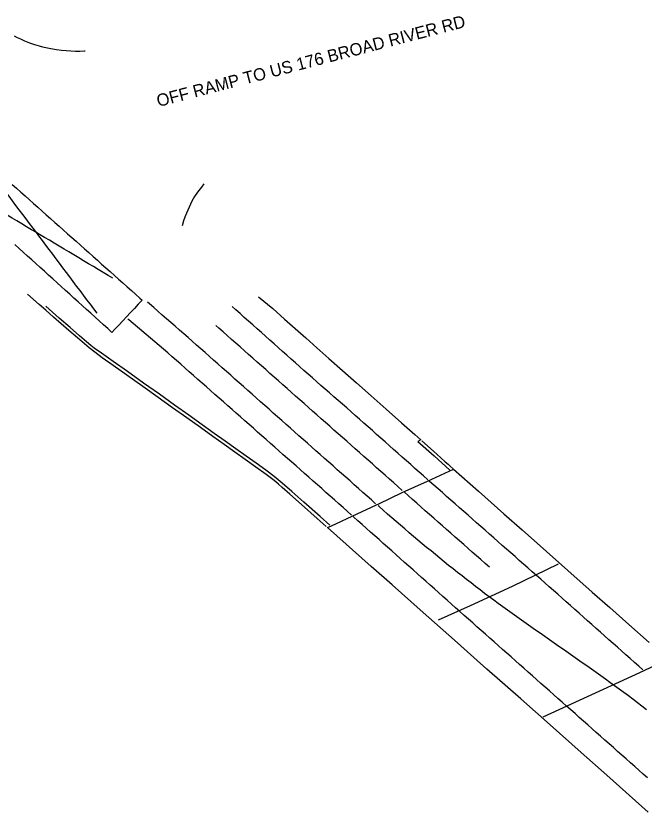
# Model space of a CAD drawing. Extents: x 1970211 to 1973046, y 801032 to 804001.
# Drawn here: x 1971353.3 to 1971628.9, y 802598.6 to 802947.9 of the extents above; entities that cross this region are included whole.
import ezdxf

# ---------------------------------------------------------------- set-up
doc = ezdxf.new("R2010")
doc.units = 0
for name, color, linetype in [('RD_EX_Bridge', 7, 'Continuous'), ('RD_EX_Bridge_Seam', 7, 'Continuous'), ('RD_EX_Conc', 7, 'Continuous'), ('RD_EX_Road', 7, 'Continuous'), ('RD_EX_Road_Paint', 7, 'Continuous'), ('RD_TX_RoadID', 7, 'Continuous')]:
    doc.layers.add(name, color=color, linetype=linetype)

msp = doc.modelspace()

# ---------------------------------------------------------------- linework, layer by layer
at = {"layer": 'RD_EX_Bridge'}
msp.add_lwpolyline([(1971630.72, 802598.58), (1971612.51, 802614.79), (1971601.37, 802624.67), (1971587.66, 802636.8), (1971574.86, 802648.23), (1971559.98, 802661.35), (1971547.12, 802672.78), (1971530.66, 802687.37), (1971518.33, 802698.31), (1971509.24, 802706.38), (1971490.01, 802723.38), (1971491.81, 802724.23), (1971503.02, 802729.5), (1971511.49, 802733.4), (1971512.58, 802733.88), (1971522.85, 802738.84), (1971533.82, 802743.75), (1971543.35, 802748.09), (1971545.36, 802749), (1971556.21, 802739.43), (1971567.44, 802729.46), (1971575.43, 802722.36), (1971586.15, 802712.88), (1971595.51, 802704.6), (1971606.18, 802695.11), (1971613.91, 802688.28), (1971622.19, 802680.91), (1971631.17, 802672.94)], dxfattribs=at)
at = {"layer": 'RD_EX_Bridge_Seam'}
for points in [[(1971538.66, 802682.92), (1971552.7, 802689.2), (1971571.13, 802697.75), (1971591.33, 802707.51)], [(1971584.66, 802640.4), (1971611.14, 802652.5), (1971618.12, 802655.75), (1971629.02, 802660.65), (1971639.02, 802665.54)]]:
    msp.add_lwpolyline(points, dxfattribs=at)
at = {"layer": 'RD_EX_Conc'}
for points in [[(1971352.57, 802939.14), (1971353.88, 802938.45), (1971355.31, 802937.78), (1971357.15, 802936.96), (1971359.26, 802936.12), (1971361.52, 802935.36), (1971363.54, 802934.75), (1971364.95, 802934.34), (1971366.42, 802933.99), (1971368.64, 802933.56), (1971371.11, 802933.16), (1971373.35, 802932.9), (1971375.43, 802932.72), (1971377.44, 802932.56), (1971379.41, 802932.46), (1971381.41, 802932.49), (1971383.44, 802932.54), (1971383.74, 802932.55)], [(1971435.83, 802874.15), (1971434.67, 802872.77), (1971432.96, 802870.54), (1971431.68, 802868.6), (1971430.54, 802866.54), (1971429.28, 802863.92), (1971428.15, 802861.39), (1971427.41, 802859.57), (1971426.84, 802857.91), (1971426.23, 802855.85)], [(1971489.45, 802723.91), (1971485.48, 802727.4), (1971478.62, 802733.46), (1971473.43, 802738.05), (1971470.11, 802741.02), (1971468.47, 802742.5), (1971467.28, 802743.54), (1971466.06, 802744.51), (1971463.15, 802746.65), (1971458.57, 802749.97), (1971453.9, 802753.32), (1971449.36, 802756.55), (1971444.68, 802759.89), (1971439.75, 802763.41), (1971434.28, 802767.31), (1971428.26, 802771.57), (1971422.08, 802775.96), (1971415.75, 802780.46), (1971409.02, 802785.25), (1971402.05, 802790.21), (1971396.04, 802794.49), (1971391.23, 802797.93), (1971387.88, 802800.36), (1971385.45, 802802.24), (1971380.34, 802806.58), (1971376.56, 802809.85), (1971369.82, 802815.71), (1971366.37, 802818.72), (1971363.47, 802821.26), (1971358.41, 802825.74)], [(1971531.34, 802761.53), (1971536.5, 802756.91), (1971539.77, 802753.98), (1971541.71, 802752.24), (1971542.9, 802751.19), (1971543.89, 802750.31), (1971545.1, 802749.23)]]:
    msp.add_lwpolyline(points, dxfattribs=at)
at = {"layer": 'RD_EX_Road'}
for points in [[(1971459.76, 802824.6), (1971466.02, 802819.47), (1971471.17, 802814.9), (1971475.84, 802810.76), (1971480.5, 802806.61), (1971485.32, 802802.32), (1971490.65, 802797.56), (1971496.54, 802792.33), (1971502.73, 802786.85), (1971509.17, 802781.17), (1971515.78, 802775.31), (1971522.44, 802769.41), (1971528.35, 802764.17), (1971530.99, 802761.84), (1971529.62, 802761.12), (1971536.75, 802754.83), (1971543.73, 802748.66)], [(1971491.09, 802724.52), (1971486.83, 802728.25), (1971479.64, 802734.57), (1971474.3, 802739.28), (1971470.08, 802742.94), (1971466.67, 802745.75), (1971462.91, 802748.61), (1971458.67, 802751.65), (1971454.28, 802754.76), (1971449.79, 802757.95), (1971445.17, 802761.25), (1971440.35, 802764.7), (1971435.04, 802768.49), (1971429.2, 802772.65), (1971422.92, 802777.12), (1971416.24, 802781.88), (1971409.29, 802786.82), (1971402.24, 802791.82), (1971395.98, 802796.24), (1971390.8, 802799.88), (1971387.63, 802802.15), (1971386.23, 802803.24), (1971384.22, 802804.95), (1971381.2, 802807.58), (1971377.11, 802811.13), (1971372.24, 802815.34), (1971366.46, 802820.56)]]:
    msp.add_lwpolyline(points, dxfattribs=at)
at = {"layer": 'RD_EX_Road_Paint'}
for points in [[(1971362.33, 802852.81), (1971360.82, 802854.8), (1971359.32, 802856.8), (1971357.82, 802858.79), (1971356.31, 802860.79), (1971354.81, 802862.79), (1971353.31, 802864.78), (1971351.8, 802866.78), (1971350.3, 802868.78), (1971348.79, 802870.77), (1971347.29, 802872.77), (1971345.79, 802874.76), (1971344.28, 802876.76), (1971342.78, 802878.76), (1971341.28, 802880.75), (1971339.77, 802882.75), (1971338.27, 802884.75), (1971338.19, 802884.85)], [(1971362.33, 802852.81), (1971360.18, 802854.09), (1971358.03, 802855.37), (1971355.89, 802856.65), (1971353.74, 802857.93), (1971351.6, 802859.21), (1971349.45, 802860.49), (1971347.3, 802861.77), (1971345.16, 802863.05), (1971343.01, 802864.33), (1971340.87, 802865.61), (1971338.72, 802866.89), (1971336.58, 802868.17), (1971334.43, 802869.45), (1971332.28, 802870.73), (1971330.14, 802872.01), (1971327.99, 802873.29), (1971325.85, 802874.57), (1971323.7, 802875.85), (1971322.18, 802876.76)], [(1971351.72, 802873.92), (1971353.59, 802872.26), (1971355.45, 802870.6), (1971357.32, 802868.94), (1971359.19, 802867.28), (1971361.05, 802865.61), (1971362.92, 802863.95), (1971364.79, 802862.29), (1971366.65, 802860.63), (1971368.52, 802858.97), (1971370.39, 802857.31), (1971372.25, 802855.65), (1971374.12, 802853.99), (1971375.99, 802852.33), (1971377.85, 802850.66), (1971379.72, 802849), (1971381.59, 802847.34), (1971383.45, 802845.68), (1971385.32, 802844.02), (1971387.19, 802842.36), (1971389.05, 802840.7), (1971390.92, 802839.04), (1971392.79, 802837.38), (1971394.65, 802835.71), (1971396.52, 802834.05), (1971398.39, 802832.39), (1971400.25, 802830.73), (1971402.12, 802829.07), (1971403.99, 802827.41), (1971405.85, 802825.75), (1971407.72, 802824.09), (1971408.68, 802823.23), (1971406.98, 802821.4), (1971405.28, 802819.57), (1971403.57, 802817.74), (1971401.87, 802815.91), (1971400.17, 802814.08), (1971398.46, 802812.25), (1971396.76, 802810.42), (1971395.47, 802809.03)], [(1971388.99, 802817.4), (1971387.49, 802819.39), (1971385.99, 802821.39), (1971384.48, 802823.39), (1971382.98, 802825.38), (1971381.48, 802827.38), (1971379.97, 802829.38), (1971378.47, 802831.37), (1971376.97, 802833.37), (1971375.46, 802835.36), (1971373.96, 802837.36), (1971372.46, 802839.36), (1971370.95, 802841.35), (1971369.45, 802843.35), (1971367.94, 802845.35), (1971366.44, 802847.34), (1971364.94, 802849.34), (1971363.43, 802851.33), (1971362.33, 802852.81)], [(1971395.87, 802832.79), (1971393.73, 802834.07), (1971391.58, 802835.35), (1971389.44, 802836.63), (1971387.29, 802837.91), (1971385.14, 802839.19), (1971383, 802840.47), (1971380.85, 802841.75), (1971378.71, 802843.03), (1971376.56, 802844.31), (1971374.42, 802845.59), (1971372.27, 802846.87), (1971370.12, 802848.15), (1971367.98, 802849.43), (1971365.83, 802850.71), (1971363.69, 802851.99), (1971362.33, 802852.81)], [(1971395.47, 802809.03), (1971393.62, 802810.71), (1971391.76, 802812.38), (1971389.91, 802814.06), (1971388.05, 802815.74), (1971386.2, 802817.41), (1971384.35, 802819.09), (1971382.49, 802820.76), (1971380.64, 802822.44), (1971378.79, 802824.11), (1971376.93, 802825.79), (1971375.08, 802827.47), (1971373.23, 802829.14), (1971371.37, 802830.82), (1971369.52, 802832.49), (1971367.66, 802834.17), (1971365.81, 802835.85), (1971363.96, 802837.52), (1971362.1, 802839.2), (1971360.25, 802840.87), (1971358.4, 802842.55), (1971356.54, 802844.22), (1971354.69, 802845.9), (1971352.84, 802847.58)], [(1971511.13, 802733.87), (1971509.26, 802735.53), (1971507.39, 802737.2), (1971505.52, 802738.86), (1971503.66, 802740.52), (1971501.79, 802742.18), (1971499.92, 802743.84), (1971498.05, 802745.49), (1971496.18, 802747.15), (1971494.31, 802748.81), (1971492.44, 802750.47), (1971490.57, 802752.12), (1971488.69, 802753.78), (1971486.82, 802755.43), (1971484.95, 802757.09), (1971483.08, 802758.75), (1971481.21, 802760.4), (1971479.34, 802762.06), (1971477.47, 802763.72), (1971475.6, 802765.38), (1971473.73, 802767.03), (1971471.86, 802768.69), (1971469.99, 802770.35), (1971468.12, 802772.01), (1971466.25, 802773.66), (1971464.38, 802775.32), (1971462.51, 802776.98), (1971460.64, 802778.64), (1971458.77, 802780.29), (1971456.9, 802781.95), (1971455.03, 802783.61), (1971453.16, 802785.27), (1971451.29, 802786.92), (1971449.42, 802788.58), (1971447.55, 802790.24), (1971445.68, 802791.9), (1971443.81, 802793.55), (1971441.94, 802795.21), (1971440.07, 802796.87), (1971438.2, 802798.53), (1971436.33, 802800.18), (1971434.46, 802801.84), (1971432.59, 802803.49), (1971430.7, 802805.14), (1971428.82, 802806.78), (1971426.94, 802808.43), (1971425.06, 802810.07), (1971423.18, 802811.72), (1971421.3, 802813.36), (1971419.42, 802815.01), (1971417.54, 802816.65), (1971415.65, 802818.3), (1971413.77, 802819.94), (1971411.89, 802821.58), (1971411.04, 802822.33)], [(1971533.98, 802744.38), (1971532.11, 802746.04), (1971530.24, 802747.7), (1971528.38, 802749.36), (1971526.51, 802751.02), (1971524.64, 802752.68), (1971522.77, 802754.34), (1971520.9, 802756), (1971519.03, 802757.66), (1971517.16, 802759.32), (1971515.3, 802760.98), (1971513.43, 802762.64), (1971511.56, 802764.3), (1971509.69, 802765.96), (1971507.82, 802767.62), (1971505.95, 802769.28), (1971504.09, 802770.94), (1971502.22, 802772.59), (1971500.33, 802774.24), (1971498.45, 802775.88), (1971496.57, 802777.53), (1971494.69, 802779.17), (1971492.81, 802780.82), (1971490.93, 802782.46), (1971489.04, 802784.11), (1971487.16, 802785.75), (1971485.28, 802787.4), (1971483.4, 802789.04), (1971481.52, 802790.69), (1971479.66, 802792.35), (1971477.79, 802794.01), (1971475.93, 802795.68), (1971474.06, 802797.34), (1971472.19, 802799), (1971470.33, 802800.66), (1971468.46, 802802.32), (1971466.6, 802803.98), (1971464.73, 802805.65), (1971462.86, 802807.31), (1971461, 802808.97), (1971459.13, 802810.63), (1971457.26, 802812.29), (1971455.39, 802813.95), (1971453.53, 802815.61), (1971451.66, 802817.27), (1971449.79, 802818.93), (1971448.18, 802820.36)], [(1971500.56, 802728.89), (1971498.69, 802730.55), (1971496.82, 802732.21), (1971494.95, 802733.87), (1971493.08, 802735.52), (1971491.21, 802737.18), (1971489.34, 802738.84), (1971487.47, 802740.5), (1971485.6, 802742.16), (1971483.73, 802743.82), (1971481.87, 802745.48), (1971479.99, 802747.13), (1971478.12, 802748.78), (1971476.24, 802750.44), (1971474.37, 802752.09), (1971472.49, 802753.74), (1971470.62, 802755.39), (1971468.74, 802757.05), (1971466.87, 802758.7), (1971465, 802760.35), (1971463.12, 802762), (1971461.25, 802763.66), (1971459.37, 802765.31), (1971457.5, 802766.96), (1971455.62, 802768.61), (1971453.75, 802770.26), (1971451.87, 802771.92), (1971450, 802773.57), (1971448.13, 802775.22), (1971446.25, 802776.87), (1971444.38, 802778.53), (1971442.5, 802780.18), (1971440.63, 802781.83), (1971438.75, 802783.48), (1971436.88, 802785.14), (1971435, 802786.79), (1971433.13, 802788.44), (1971431.25, 802790.09), (1971429.38, 802791.74), (1971427.51, 802793.4), (1971425.63, 802795.05), (1971423.76, 802796.7), (1971421.88, 802798.35), (1971420.01, 802800.01), (1971418.11, 802801.63), (1971416.2, 802803.24), (1971414.29, 802804.86), (1971412.38, 802806.47), (1971410.48, 802808.08), (1971408.57, 802809.7), (1971406.66, 802811.31), (1971404.75, 802812.92), (1971402.84, 802814.54), (1971402.44, 802814.88)], [(1971522.81, 802739.72), (1971520.94, 802741.38), (1971519.07, 802743.03), (1971517.2, 802744.69), (1971515.32, 802746.34), (1971513.45, 802748), (1971511.58, 802749.66), (1971509.71, 802751.31), (1971507.84, 802752.97), (1971505.97, 802754.62), (1971504.09, 802756.28), (1971502.22, 802757.93), (1971500.35, 802759.59), (1971498.48, 802761.25), (1971496.61, 802762.9), (1971494.74, 802764.56), (1971492.86, 802766.21), (1971490.99, 802767.87), (1971489.12, 802769.52), (1971487.25, 802771.18), (1971485.38, 802772.84), (1971483.51, 802774.49), (1971481.63, 802776.15), (1971479.76, 802777.8), (1971477.89, 802779.46), (1971476.02, 802781.12), (1971474.15, 802782.77), (1971472.28, 802784.43), (1971470.4, 802786.08), (1971468.53, 802787.74), (1971466.66, 802789.39), (1971464.79, 802791.05), (1971462.92, 802792.71), (1971461.05, 802794.36), (1971459.17, 802796.02), (1971457.3, 802797.67), (1971455.43, 802799.33), (1971453.56, 802800.99), (1971451.69, 802802.64), (1971449.82, 802804.3), (1971447.94, 802805.95), (1971446.07, 802807.61), (1971444.2, 802809.26), (1971442.33, 802810.92), (1971441.06, 802812.04)], [(1971628.42, 802660.92), (1971626.55, 802662.58), (1971624.69, 802664.25), (1971622.82, 802665.91), (1971620.95, 802667.57), (1971619.08, 802669.23), (1971617.21, 802670.89), (1971615.34, 802672.55), (1971613.48, 802674.21), (1971611.61, 802675.87), (1971609.74, 802677.53), (1971607.87, 802679.19), (1971606, 802680.85), (1971604.13, 802682.51), (1971602.27, 802684.17), (1971600.4, 802685.83), (1971598.53, 802687.49), (1971596.66, 802689.15), (1971594.79, 802690.81), (1971592.92, 802692.47), (1971591.05, 802694.13), (1971589.19, 802695.79), (1971587.31, 802697.45), (1971585.44, 802699.1), (1971583.56, 802700.75), (1971581.69, 802702.4), (1971579.81, 802704.05), (1971577.94, 802705.7), (1971576.06, 802707.36), (1971574.18, 802709.01), (1971572.31, 802710.66), (1971570.43, 802712.31), (1971568.56, 802713.96), (1971566.68, 802715.61), (1971564.8, 802717.26), (1971562.93, 802718.92), (1971561.05, 802720.57), (1971559.18, 802722.22), (1971557.3, 802723.87), (1971555.43, 802725.52), (1971553.55, 802727.17), (1971551.67, 802728.83), (1971549.8, 802730.48), (1971547.92, 802732.13), (1971546.05, 802733.78), (1971544.17, 802735.43), (1971542.29, 802737.08), (1971540.42, 802738.74), (1971538.54, 802740.39), (1971536.67, 802742.04), (1971534.79, 802743.69), (1971534.67, 802743.8)], [(1971561.06, 802706.03), (1971559.18, 802707.69), (1971557.3, 802709.34), (1971555.43, 802710.99), (1971553.55, 802712.64), (1971551.67, 802714.29), (1971549.8, 802715.94), (1971547.92, 802717.59), (1971546.05, 802719.24), (1971544.17, 802720.89), (1971542.29, 802722.55), (1971540.42, 802724.2), (1971538.54, 802725.85), (1971536.67, 802727.5), (1971534.79, 802729.15), (1971532.91, 802730.8), (1971531.04, 802732.45), (1971529.16, 802734.1), (1971527.28, 802735.75), (1971525.41, 802737.41), (1971523.74, 802738.88)], [(1971629.99, 802643.5), (1971628, 802645.02), (1971626.02, 802646.54), (1971624.03, 802648.06), (1971622.05, 802649.58), (1971620.06, 802651.1), (1971618.03, 802652.55), (1971615.99, 802654), (1971613.96, 802655.46), (1971611.93, 802656.91), (1971609.9, 802658.37), (1971607.85, 802659.81), (1971605.81, 802661.25), (1971603.76, 802662.68), (1971601.72, 802664.12), (1971599.68, 802665.56), (1971597.63, 802667), (1971595.58, 802668.43), (1971593.54, 802669.87), (1971591.49, 802671.3), (1971589.44, 802672.74), (1971587.39, 802674.17), (1971585.34, 802675.59), (1971583.28, 802677.01), (1971581.23, 802678.43), (1971579.17, 802679.85), (1971577.13, 802681.3), (1971575.1, 802682.76), (1971573.07, 802684.21), (1971571.04, 802685.67), (1971569.01, 802687.13), (1971566.98, 802688.59), (1971564.96, 802690.05), (1971562.94, 802691.53), (1971560.93, 802693.02), (1971558.93, 802694.52), (1971556.96, 802696.04), (1971554.98, 802697.57), (1971553, 802699.09), (1971551.02, 802700.62), (1971549.05, 802702.16), (1971547.09, 802703.72), (1971545.13, 802705.27), (1971543.17, 802706.82), (1971541.22, 802708.38), (1971539.29, 802709.96), (1971537.36, 802711.55), (1971535.43, 802713.14), (1971533.49, 802714.72), (1971531.57, 802716.32), (1971529.66, 802717.94), (1971527.76, 802719.55), (1971525.85, 802721.17), (1971523.95, 802722.79), (1971522.04, 802724.4), (1971520.15, 802726.03), (1971518.27, 802727.68), (1971516.38, 802729.32), (1971514.5, 802730.97), (1971512.62, 802732.61), (1971512.28, 802732.91)], [(1971630.4, 802613.58), (1971628.53, 802615.24), (1971626.66, 802616.9), (1971624.79, 802618.56), (1971622.92, 802620.22), (1971621.05, 802621.88), (1971619.18, 802623.53), (1971617.31, 802625.19), (1971615.44, 802626.85), (1971613.57, 802628.51), (1971611.7, 802630.17), (1971609.83, 802631.83), (1971607.96, 802633.48), (1971606.09, 802635.14), (1971604.22, 802636.8), (1971602.35, 802638.46), (1971600.48, 802640.12), (1971598.61, 802641.78), (1971596.74, 802643.43), (1971594.87, 802645.09), (1971593, 802646.75), (1971591.13, 802648.41), (1971589.26, 802650.07), (1971587.39, 802651.73), (1971585.52, 802653.38), (1971583.65, 802655.04), (1971581.78, 802656.7), (1971579.91, 802658.36), (1971578.04, 802660.02), (1971576.17, 802661.68), (1971574.3, 802663.34), (1971572.43, 802664.99), (1971570.56, 802666.65), (1971568.69, 802668.31), (1971566.82, 802669.97), (1971564.95, 802671.63), (1971563.08, 802673.29), (1971561.21, 802674.94), (1971559.34, 802676.6), (1971557.47, 802678.26), (1971555.6, 802679.92), (1971553.73, 802681.58), (1971551.86, 802683.24), (1971549.99, 802684.89), (1971548.12, 802686.55), (1971546.25, 802688.21), (1971544.38, 802689.87), (1971542.51, 802691.53), (1971540.64, 802693.19), (1971538.77, 802694.85), (1971536.91, 802696.51), (1971535.04, 802698.17), (1971533.17, 802699.84), (1971531.3, 802701.5), (1971529.44, 802703.16), (1971527.57, 802704.82), (1971525.7, 802706.48), (1971523.84, 802708.14), (1971521.97, 802709.8), (1971520.1, 802711.46), (1971518.23, 802713.13), (1971516.37, 802714.79), (1971514.5, 802716.45), (1971512.63, 802718.11), (1971510.77, 802719.77), (1971508.9, 802721.43), (1971507.03, 802723.09), (1971505.16, 802724.76), (1971503.3, 802726.42), (1971501.43, 802728.08), (1971501.3, 802728.19)]]:
    msp.add_lwpolyline(points, dxfattribs=at)

# ---------------------------------------------------------------- texts
at = {"layer": 'RD_TX_RoadID'}
msp.add_text('OFF RAMP TO US 176 BROAD RIVER RD', height=5.4, rotation=14.6, dxfattribs=at).set_placement((1971415.84, 802907.9))

doc.saveas('drawing.dxf')
